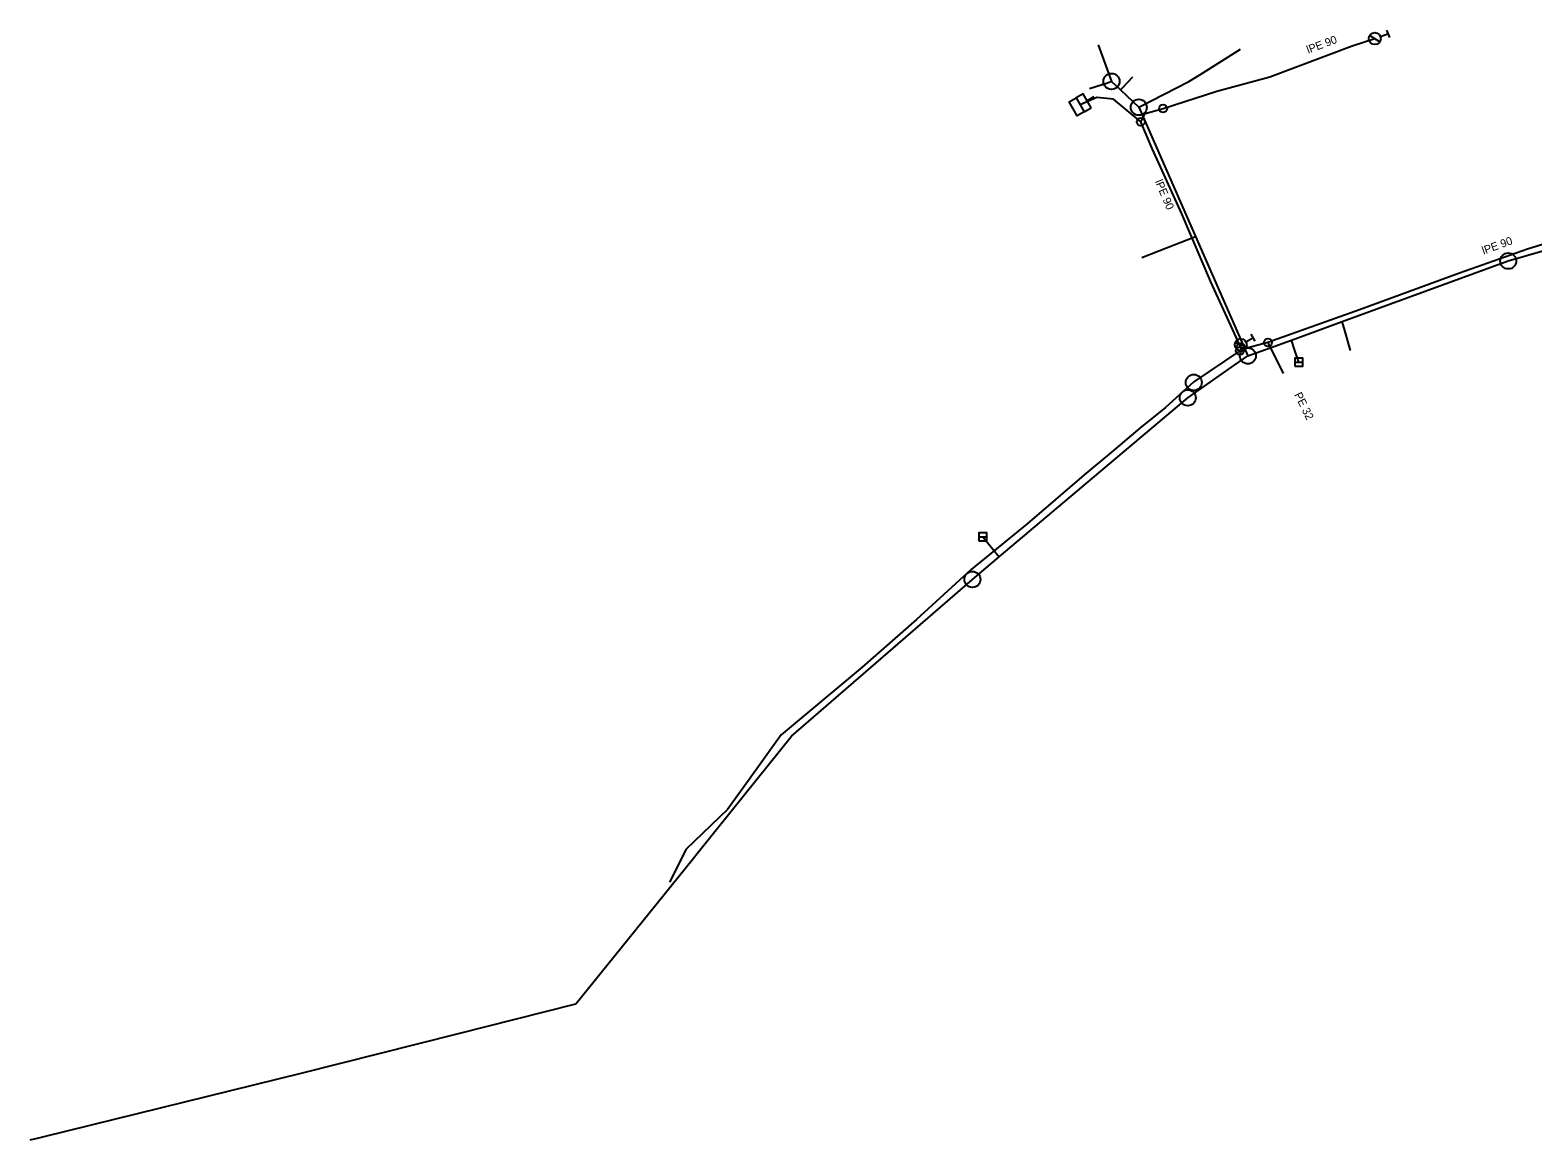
# Model space of a CAD drawing. Extents: x -770550 to -770198, y -1055065 to -1054790.
# Drawn here: x -770550.3 to -770362.5, y -1055065 to -1054926.3 of the extents above; entities that cross this region are included whole.
import ezdxf

# ---------------------------------------------------------------- set-up
doc = ezdxf.new("R2010")
doc.units = 0
doc.layers.add('Level 0', color=7, linetype='Continuous')

msp = doc.modelspace()

# ---------------------------------------------------------------- linework, layer by layer
at = {"layer": 'Level 0'}
for p, q in [((-770382.93, -1054926.99), (-770381.65, -1054927.78)), ((-770381.59, -1054927.12), (-770380.65, -1054926.78)), ((-770380.82, -1054926.31), (-770380.47, -1054927.25)), ((-770416.87, -1054928.14), (-770415.19, -1054932.72)), ((-770404.15, -1054931.89), (-770399.05, -1054928.69)), ((-770395.39, -1054932.14), (-770385.11, -1054928.27)), ((-770385.11, -1054928.27), (-770382.29, -1054927.38)), ((-770412.58, -1054932.2), (-770413.86, -1054933.55)), ((-770405.51, -1054932.75), (-770404.15, -1054931.89)), ((-770402.01, -1054933.96), (-770395.39, -1054932.14)), ((-770415.7, -1054932.96), (-770417.94, -1054933.64)), ((-770415.19, -1054932.72), (-770415.7, -1054932.96)), ((-770415.19, -1054932.72), (-770414.21, -1054933.65)), ((-770414.21, -1054933.65), (-770414.08, -1054933.78)), ((-770413.86, -1054933.55), (-770414.08, -1054933.78)), ((-770414.08, -1054933.78), (-770411.78, -1054935.96)), ((-770411.78, -1054935.96), (-770405.51, -1054932.75)), ((-770408.75, -1054936.12), (-770402.01, -1054933.96)), ((-770417.03, -1054934.74), (-770419.12, -1054935.64)), ((-770417.39, -1054934.64), (-770418.25, -1054935.14)), ((-770414.94, -1054934.95), (-770417.03, -1054934.74)), ((-770411.53, -1054937.77), (-770414.94, -1054934.95)), ((-770411.78, -1054935.96), (-770404.68, -1054952.08)), ((-770410.97, -1054936.72), (-770408.75, -1054936.12)), ((-770411.53, -1054937.77), (-770410.97, -1054936.72)), ((-770410.1, -1054941.12), (-770411.53, -1054937.77)), ((-770406.41, -1054949.25), (-770410.1, -1054941.12)), ((-770402.77, -1054957.78), (-770406.41, -1054949.25)), ((-770347.91, -1054948.93), (-770363.2, -1054953.68)), ((-770365.61, -1054955.16), (-770350.96, -1054950.9)), ((-770409.29, -1054953.88), (-770404.68, -1054952.08)), ((-770404.68, -1054952.08), (-770398.14, -1054967.01)), ((-770411.42, -1054954.71), (-770409.29, -1054953.88)), ((-770386.37, -1054962.72), (-770365.61, -1054955.16)), ((-770363.2, -1054953.68), (-770371.69, -1054956.68)), ((-770371.69, -1054956.68), (-770384.2, -1054961.25)), ((-770399.17, -1054965.68), (-770402.77, -1054957.78)), ((-770384.2, -1054961.25), (-770395.64, -1054965.35)), ((-770397.77, -1054964.31), (-770397.27, -1054965.18)), ((-770392.71, -1054965.03), (-770386.37, -1054962.72)), ((-770386.04, -1054963.85), (-770386.37, -1054962.72)), ((-770385.31, -1054966.36), (-770386.04, -1054963.85)), ((-770399.14, -1054966.38), (-770404.91, -1054970.25)), ((-770399.73, -1054965.34), (-770398.34, -1054965.9)), ((-770399.04, -1054965.62), (-770399.17, -1054965.68)), ((-770399.06, -1054965.91), (-770399.17, -1054965.68)), ((-770398.91, -1054966.29), (-770399.14, -1054966.38)), ((-770398.91, -1054966.29), (-770399.06, -1054965.91)), ((-770398.28, -1054966.04), (-770398.91, -1054966.29)), ((-770398.39, -1054965.25), (-770397.52, -1054964.75)), ((-770395.64, -1054965.35), (-770398.28, -1054966.04)), ((-770398.14, -1054967.01), (-770392.71, -1054965.03)), ((-770395.64, -1054965.35), (-770393.72, -1054969.23)), ((-770392.36, -1054966.09), (-770392.71, -1054965.03)), ((-770391.8, -1054967.79), (-770392.36, -1054966.09)), ((-770405.66, -1054972.25), (-770399.78, -1054968.15)), ((-770399.78, -1054968.15), (-770398.14, -1054967.01)), ((-770392.3, -1054967.79), (-770391.3, -1054967.79)), ((-770404.91, -1054970.25), (-770408.43, -1054973.48)), ((-770429.22, -1054992.12), (-770405.66, -1054972.25)), ((-770408.43, -1054973.48), (-770411.64, -1054976.03)), ((-770411.64, -1054976.03), (-770415.17, -1054979.05)), ((-770415.17, -1054979.05), (-770418.66, -1054981.92)), ((-770418.66, -1054981.92), (-770425.72, -1054988.01)), ((-770425.72, -1054988.01), (-770432.71, -1054993.72)), ((-770431.76, -1054989.61), (-770430.76, -1054989.61)), ((-770431.26, -1054989.61), (-770429.22, -1054992.12)), ((-770432.57, -1054994.94), (-770429.22, -1054992.12)), ((-770432.71, -1054993.72), (-770439.55, -1054999.95)), ((-770455.16, -1055014.53), (-770432.57, -1054994.94)), ((-770439.55, -1054999.95), (-770446.36, -1055005.88)), ((-770446.36, -1055005.88), (-770456.48, -1055014.37)), ((-770461, -1055021.77), (-770455.16, -1055014.53)), ((-770456.48, -1055014.37), (-770460.69, -1055020.21)), ((-770460.69, -1055020.21), (-770463.19, -1055023.69)), ((-770466.98, -1055029.18), (-770461, -1055021.77)), ((-770463.19, -1055023.69), (-770468.34, -1055028.62)), ((-770477.38, -1055042.08), (-770467.43, -1055029.74)), ((-770468.34, -1055028.62), (-770470.43, -1055032.76)), ((-770467.43, -1055029.74), (-770466.98, -1055029.18)), ((-770482.11, -1055047.94), (-770477.38, -1055042.08)), ((-770493.51, -1055050.82), (-770482.11, -1055047.94)), ((-770496.3, -1055051.53), (-770493.51, -1055050.82)), ((-770516.45, -1055056.62), (-770496.94, -1055051.69)), ((-770496.94, -1055051.69), (-770496.3, -1055051.53)), ((-770548.57, -1055064.53), (-770516.45, -1055056.62)), ((-770550.32, -1055064.96), (-770549.24, -1055064.69)), ((-770549.24, -1055064.69), (-770548.57, -1055064.53))]:
    msp.add_line(p, q, dxfattribs=at)
for points in [[(-770417.75, -1054936.01), (-770418.75, -1054934.27), (-770419.62, -1054934.77), (-770418.62, -1054936.51)], [(-770392.3, -1054968.29), (-770391.3, -1054968.29), (-770391.3, -1054967.29), (-770392.3, -1054967.29)], [(-770431.76, -1054990.11), (-770430.76, -1054990.11), (-770430.76, -1054989.11), (-770431.76, -1054989.11)]]:
    msp.add_lwpolyline(points, close=True, dxfattribs=at)
msp.add_lwpolyline([(-770418.62, -1054936.51), (-770419.49, -1054937.01), (-770420.49, -1054935.27), (-770419.62, -1054934.77)], dxfattribs=at)
for centre, radius in [((-770382.29, -1054927.38), 0.75), ((-770415.19, -1054932.72), 1), ((-770411.78, -1054935.96), 1), ((-770408.75, -1054936.12), 0.5), ((-770411.53, -1054937.77), 0.5), ((-770365.61, -1054955.16), 1), ((-770399.04, -1054965.62), 0.75), ((-770399.14, -1054966.38), 0.5), ((-770399.06, -1054965.91), 0.5), ((-770398.14, -1054967.01), 1), ((-770395.64, -1054965.35), 0.5), ((-770404.91, -1054970.34), 1), ((-770405.66, -1054972.25), 1), ((-770432.57, -1054994.94), 1)]:
    msp.add_circle(centre, radius, dxfattribs=at)

# ---------------------------------------------------------------- texts
for s, rotation, p in [('lPE 90', 20.629, (-770390.6, -1054929.27)), ('lPE 90', 293.116, (-770409.79, -1054945.24)), ('lPE 90', 20.068, (-770368.69, -1054954.37)), ('PE 32', 296.27, (-770392.38, -1054971.86))]:
    msp.add_text(s, height=1, rotation=rotation, dxfattribs=at).set_placement(p)

doc.saveas('drawing.dxf')
